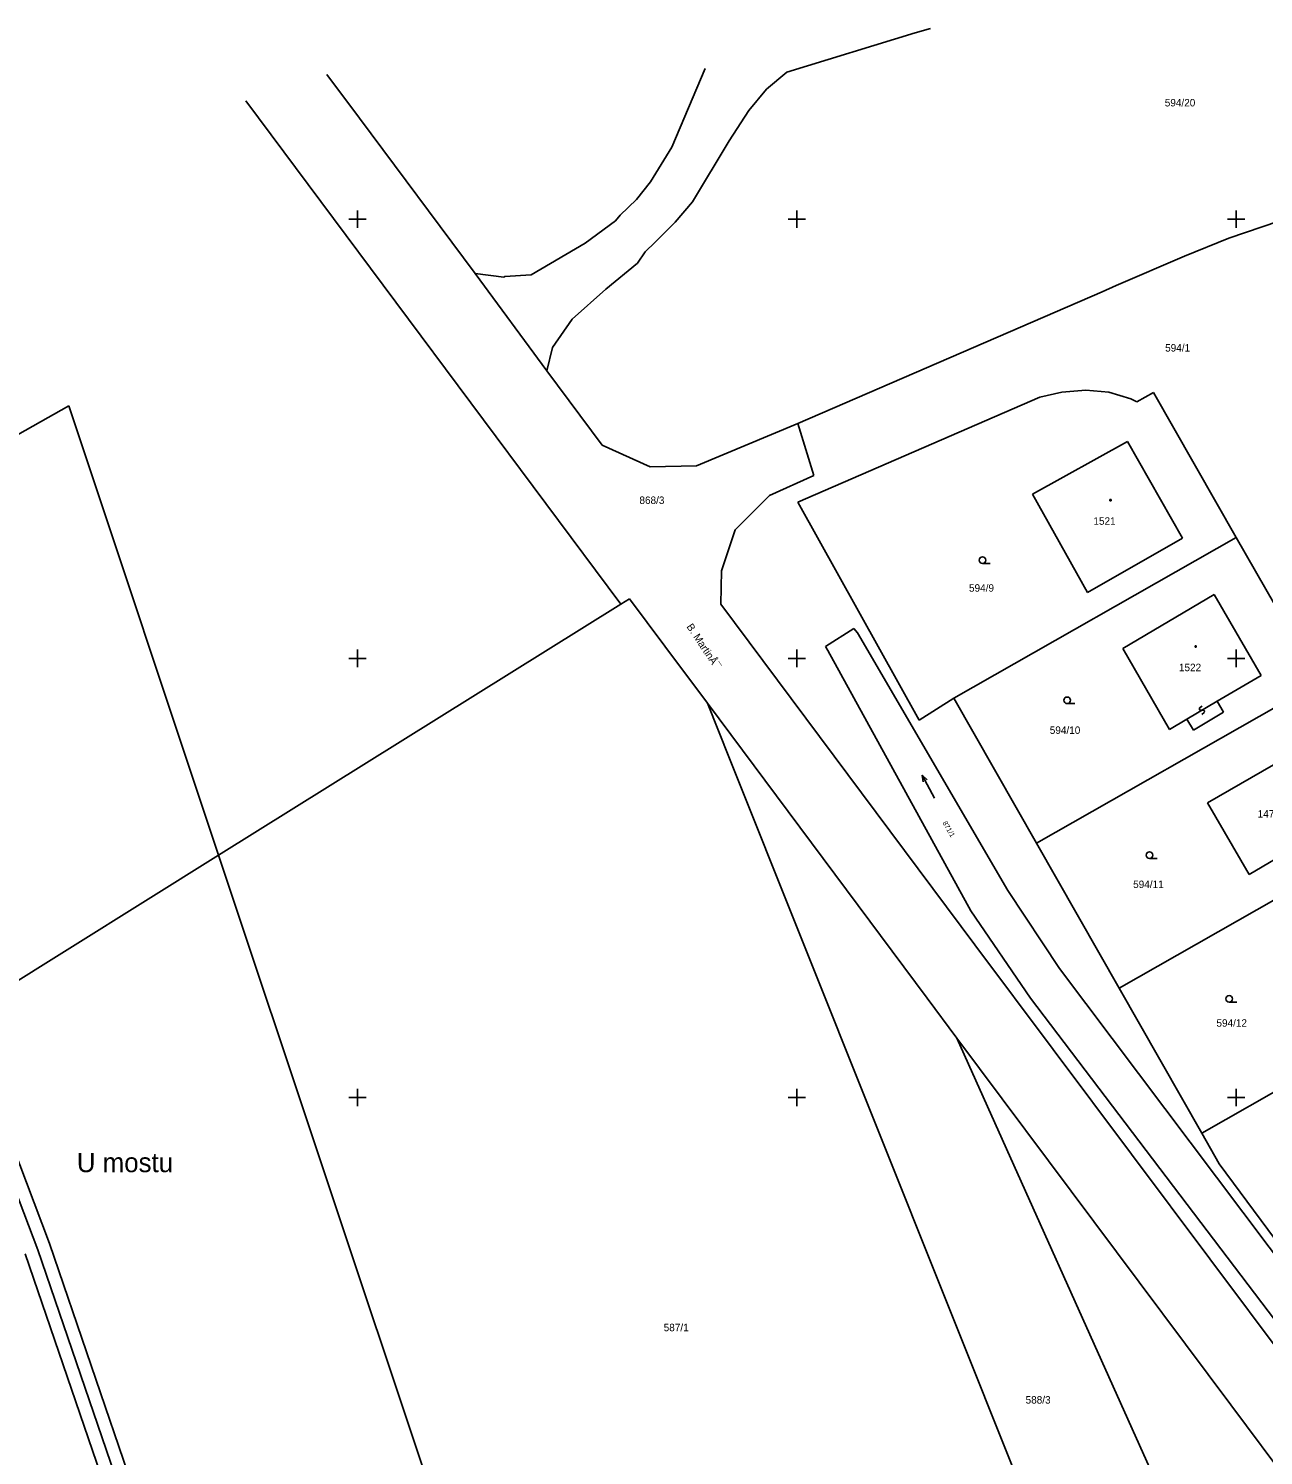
# Model space of a CAD drawing. Extents: x -493648 to -493033, y -1127718 to -1127026.
# Drawn here: x -493437.4 to -493296.9, y -1127190.8 to -1127028.3 of the extents above; entities that cross this region are included whole.
import ezdxf

# ---------------------------------------------------------------- set-up
doc = ezdxf.new("R2010")
doc.units = 0
doc.layers.add('katastrální mapa', color=7, linetype='Continuous')
doc.layers.add('síť', color=7, linetype='Continuous')

msp = doc.modelspace()

# ---------------------------------------------------------------- linework, layer by layer
at = {"layer": 'katastrální mapa'}
for p, q in [((-493351.12, -1127033.25), (-493336.51, -1127028.79)), ((-493336.51, -1127028.79), (-493334.79, -1127028.29)), ((-493403.49, -1127033.52), (-493399.77, -1127038.5)), ((-493364.22, -1127041.78), (-493360.41, -1127032.85)), ((-493353.43, -1127035.19), (-493351.12, -1127033.25)), ((-493355.46, -1127037.63), (-493353.43, -1127035.19)), ((-493412.71, -1127036.52), (-493370.04, -1127093.84)), ((-493399.77, -1127038.5), (-493386.62, -1127056.17)), ((-493357.71, -1127041.07), (-493355.46, -1127037.63)), ((-493366.66, -1127045.73), (-493364.22, -1127041.78)), ((-493361.87, -1127048.03), (-493357.71, -1127041.07)), ((-493368.23, -1127047.77), (-493366.66, -1127045.73)), ((-493370.1, -1127049.54), (-493368.23, -1127047.77)), ((-493363.84, -1127050.35), (-493361.87, -1127048.03)), ((-493300.84, -1127052.16), (-493287.07, -1127047.5)), ((-493374.07, -1127052.73), (-493370.64, -1127050.19)), ((-493370.64, -1127050.19), (-493370.1, -1127049.54)), ((-493366.11, -1127052.6), (-493363.84, -1127050.35)), ((-493305.87, -1127054.19), (-493300.84, -1127052.16)), ((-493380.24, -1127056.35), (-493374.07, -1127052.73)), ((-493368.13, -1127054.99), (-493367.25, -1127053.73)), ((-493367.25, -1127053.73), (-493366.11, -1127052.6)), ((-493371.72, -1127057.96), (-493368.13, -1127054.99)), ((-493313.64, -1127057.55), (-493305.87, -1127054.19)), ((-493386.62, -1127056.17), (-493378.45, -1127067.27)), ((-493386.62, -1127056.17), (-493383.35, -1127056.58)), ((-493383.35, -1127056.58), (-493383.21, -1127056.51)), ((-493383.21, -1127056.51), (-493380.24, -1127056.35)), ((-493375.58, -1127061.37), (-493371.72, -1127057.96)), ((-493349.9, -1127073.27), (-493315.23, -1127058.26)), ((-493315.23, -1127058.26), (-493313.64, -1127057.55)), ((-493377.8, -1127064.59), (-493375.58, -1127061.37)), ((-493378.45, -1127067.27), (-493377.8, -1127064.59)), ((-493378.45, -1127067.27), (-493372.17, -1127075.73)), ((-493322.35, -1127070.27), (-493319.83, -1127069.68)), ((-493319.83, -1127069.68), (-493317.09, -1127069.45)), ((-493317.09, -1127069.45), (-493314.49, -1127069.71)), ((-493314.49, -1127069.71), (-493311.98, -1127070.44)), ((-493311.29, -1127070.81), (-493309.39, -1127069.73)), ((-493309.39, -1127069.73), (-493299.98, -1127086.23)), ((-493461.97, -1127087.61), (-493432.84, -1127071.26)), ((-493432.84, -1127071.26), (-493415.8, -1127122.41)), ((-493349.89, -1127082.23), (-493322.35, -1127070.27)), ((-493311.98, -1127070.44), (-493311.29, -1127070.81)), ((-493361.4, -1127078.07), (-493349.9, -1127073.27)), ((-493349.9, -1127073.27), (-493348.05, -1127079.19)), ((-493372.17, -1127075.73), (-493366.67, -1127078.2)), ((-493323.19, -1127081.32), (-493312.36, -1127075.32)), ((-493312.36, -1127075.32), (-493306.09, -1127086.31)), ((-493366.67, -1127078.2), (-493361.4, -1127078.07)), ((-493353.1, -1127081.47), (-493348.05, -1127079.19)), ((-493323.19, -1127081.32), (-493316.92, -1127092.5)), ((-493357.01, -1127085.37), (-493353.1, -1127081.47)), ((-493349.89, -1127082.23), (-493336.07, -1127107.03)), ((-493314.37, -1127081.92), (-493314.22, -1127081.92)), ((-493314.37, -1127082.07), (-493314.37, -1127081.92)), ((-493314.22, -1127082.07), (-493314.37, -1127082.07)), ((-493314.22, -1127081.92), (-493314.22, -1127082.07)), ((-493358.58, -1127090.04), (-493357.01, -1127085.37)), ((-493332.13, -1127104.54), (-493299.98, -1127086.23)), ((-493316.92, -1127092.5), (-493306.09, -1127086.31)), ((-493299.98, -1127086.23), (-493290.57, -1127102.74)), ((-493328.87, -1127089.19), (-493327.99, -1127089.19)), ((-493358.63, -1127093.83), (-493358.58, -1127090.04)), ((-493312.91, -1127098.88), (-493302.49, -1127092.74)), ((-493302.49, -1127092.74), (-493297.16, -1127101.95)), ((-493415.8, -1127122.41), (-493370.04, -1127093.84)), ((-493370.04, -1127093.84), (-493369.03, -1127093.21)), ((-493369.03, -1127093.21), (-493365.01, -1127098.6)), ((-493358.63, -1127093.83), (-493329.74, -1127132.61)), ((-493346.75, -1127098.66), (-493343.49, -1127096.61)), ((-493343.49, -1127096.61), (-493343.11, -1127097.1)), ((-493343.11, -1127097.1), (-493325.98, -1127126.44)), ((-493365.01, -1127098.6), (-493360.16, -1127105.11)), ((-493346.75, -1127098.66), (-493346.46, -1127099.09)), ((-493346.46, -1127099.09), (-493330.21, -1127128.74)), ((-493312.91, -1127098.88), (-493307.59, -1127108.09)), ((-493304.68, -1127098.59), (-493304.53, -1127098.59)), ((-493304.68, -1127098.74), (-493304.68, -1127098.59)), ((-493304.53, -1127098.74), (-493304.68, -1127098.74)), ((-493304.53, -1127098.59), (-493304.53, -1127098.74)), ((-493302.16, -1127104.89), (-493297.16, -1127101.95)), ((-493322.72, -1127121.05), (-493290.57, -1127102.74)), ((-493360.16, -1127105.11), (-493357.65, -1127111.4)), ((-493360.16, -1127105.11), (-493335.18, -1127138.67)), ((-493336.07, -1127107.03), (-493332.13, -1127104.54)), ((-493332.13, -1127104.54), (-493322.72, -1127121.05)), ((-493319.24, -1127105.15), (-493318.36, -1127105.15)), ((-493305.61, -1127106.92), (-493302.16, -1127104.89)), ((-493304.15, -1127105.65), (-493304.18, -1127105.79)), ((-493304.18, -1127105.79), (-493304.13, -1127105.88)), ((-493303.87, -1127105.43), (-493304.15, -1127105.65)), ((-493302.16, -1127104.89), (-493301.42, -1127106.14)), ((-493307.59, -1127108.09), (-493305.61, -1127106.92)), ((-493305.61, -1127106.92), (-493304.87, -1127108.17)), ((-493304.87, -1127108.17), (-493301.42, -1127106.14)), ((-493304.13, -1127105.88), (-493304, -1127105.91)), ((-493304, -1127105.91), (-493303.77, -1127105.9)), ((-493303.62, -1127106.16), (-493303.9, -1127106.38)), ((-493303.77, -1127105.9), (-493303.64, -1127105.93)), ((-493303.64, -1127105.93), (-493303.59, -1127106.02)), ((-493303.59, -1127106.02), (-493303.62, -1127106.16)), ((-493303.26, -1127116.46), (-493292.38, -1127110.16)), ((-493357.65, -1127111.4), (-493312.38, -1127224.74)), ((-493334.31, -1127115.93), (-493335.73, -1127113.29)), ((-493335.73, -1127113.29), (-493335.6, -1127114.07)), ((-493335.73, -1127113.29), (-493335.16, -1127113.83)), ((-493303.26, -1127116.46), (-493298.53, -1127124.59)), ((-493298.53, -1127124.59), (-493287.71, -1127118.23)), ((-493313.32, -1127137.56), (-493281.17, -1127119.25)), ((-493322.72, -1127121.05), (-493313.32, -1127137.56)), ((-493444.9, -1127140.58), (-493415.8, -1127122.41)), ((-493415.8, -1127122.41), (-493388.48, -1127204.39)), ((-493309.87, -1127122.77), (-493308.99, -1127122.77)), ((-493325.98, -1127126.44), (-493320.1, -1127135.31)), ((-493330.21, -1127128.74), (-493323.39, -1127138.67)), ((-493329.74, -1127132.61), (-493294.06, -1127180.27)), ((-493320.1, -1127135.31), (-493282.06, -1127185.95)), ((-493303.92, -1127154.07), (-493271.77, -1127135.76)), ((-493313.32, -1127137.56), (-493303.92, -1127154.07)), ((-493335.18, -1127138.67), (-493331.77, -1127143.24)), ((-493323.39, -1127138.67), (-493285.46, -1127188.73)), ((-493300.79, -1127139.15), (-493299.91, -1127139.15)), ((-493446.22, -1127141.41), (-493436.38, -1127167.36)), ((-493444.9, -1127140.58), (-493435.05, -1127166.63)), ((-493331.77, -1127143.24), (-493299.89, -1127214.33)), ((-493331.77, -1127143.24), (-493300.59, -1127184.98)), ((-493303.92, -1127154.07), (-493301.94, -1127157.55)), ((-493301.94, -1127157.55), (-493292.95, -1127169.69)), ((-493436.38, -1127167.36), (-493403.55, -1127263.33)), ((-493435.05, -1127166.63), (-493402.21, -1127262.67)), ((-493437.82, -1127167.8), (-493404.97, -1127263.84)), ((-493300.59, -1127184.98), (-493283.37, -1127208.04))]:
    msp.add_line(p, q, dxfattribs=at)
for centre in [(-493328.87, -1127088.815), (-493319.24, -1127104.775), (-493309.87, -1127122.395), (-493300.79, -1127138.775)]:
    msp.add_circle(centre, 0.375, dxfattribs=at)
at = {"layer": 'síť'}
for p, q in [((-493401, -1127050), (-493399, -1127050)), ((-493400, -1127049), (-493400, -1127051)), ((-493351, -1127050), (-493349, -1127050)), ((-493350, -1127049), (-493350, -1127051)), ((-493301, -1127050), (-493299, -1127050)), ((-493300, -1127049), (-493300, -1127051)), ((-493400, -1127099), (-493400, -1127101)), ((-493350, -1127099), (-493350, -1127101)), ((-493300, -1127099), (-493300, -1127101)), ((-493401, -1127100), (-493399, -1127100)), ((-493351, -1127100), (-493349, -1127100)), ((-493301, -1127100), (-493299, -1127100)), ((-493400, -1127149), (-493400, -1127151)), ((-493350, -1127149), (-493350, -1127151)), ((-493300, -1127149), (-493300, -1127151)), ((-493401, -1127150), (-493399, -1127150)), ((-493351, -1127150), (-493349, -1127150)), ((-493301, -1127150), (-493299, -1127150))]:
    msp.add_line(p, q, dxfattribs=at)

# ---------------------------------------------------------------- texts
at = {"layer": 'katastrální mapa'}
for s, height, p in [('594/20', 0.849996, (-493308.12, -1127037.16)), ('594/1', 0.849996, (-493308.08, -1127065.07)), ('868/3', 0.849996, (-493367.91, -1127082.42)), ('1521', 0.849996, (-493316.24, -1127084.79)), ('594/9', 0.849996, (-493330.4, -1127092.41)), ('1522', 0.849996, (-493306.51, -1127101.46)), ('594/10', 0.849996, (-493321.21, -1127108.6)), ('1478', 0.849996, (-493297.55, -1127118.13)), ('594/11', 0.849996, (-493311.72, -1127126.15)), ('594/12', 0.849996, (-493302.24, -1127141.94)), ('U mostu', 2.199996, (-493431.94, -1127158.5)), ('587/1', 0.849996, (-493365.15, -1127176.61)), ('588/3', 0.849996, (-493323.96, -1127184.85))]:
    msp.add_text(s, height=height, dxfattribs=at).set_placement(p)
for s, height, rotation, p in [('B. MartinÅ¯', 0.849996, 303.6762, (-493362.59, -1127096.39)), ('871/1', 0.569994, 300.2513389, (-493333.44, -1127118.73))]:
    msp.add_text(s, height=height, rotation=rotation, dxfattribs=at).set_placement(p)

doc.saveas('drawing.dxf')
